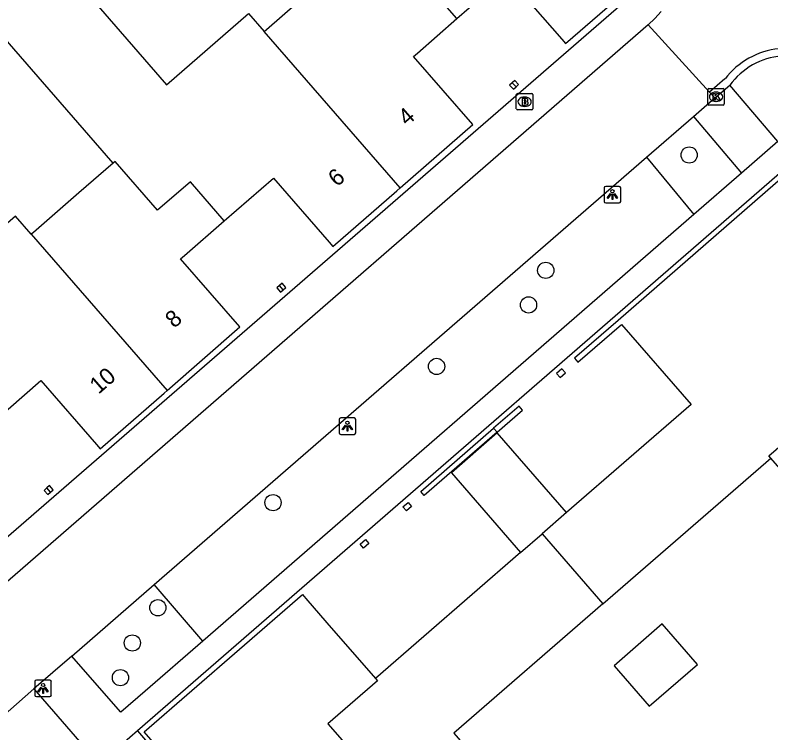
# Model space of a CAD drawing. Extents: x 155888 to 156864, y 383882 to 384671.
# Drawn here: x 156181.97 to 156227.53, y 384100.28 to 384143.54 of the extents above; entities that cross this region are included whole.
import ezdxf

# ---------------------------------------------------------------- set-up
doc = ezdxf.new("R2010")
doc.units = 0
for name, color, linetype in [('IMGEO_Boom', 7, 'Continuous'), ('IMGEO_Brandkraan', 7, 'Continuous'), ('IMGEO_Kolk', 7, 'Continuous'), ('IMGEO_Lichtpunt', 7, 'Continuous'), ('IMGEO_Pand', 7, 'Continuous'), ('IMGEO_Pand_nummerreeks', 7, 'Continuous'), ('IMGEO_Parkeervlak_open', 7, 'Continuous'), ('IMGEO_Rijbaan_lokaal_gesloten', 7, 'Continuous'), ('IMGEO_Rijbaan_lokaal_open', 7, 'Continuous'), ('IMGEO_Voetpad_open', 7, 'Continuous')]:
    doc.layers.add(name, color=color, linetype=linetype)

msp = doc.modelspace()

# ---------------------------------------------------------------- linework, layer by layer
at = {"layer": 'IMGEO_Boom'}
for centre in [(156222.605, 384135.111), (156213.959, 384128.157), (156212.921, 384126.074), (156207.375, 384122.368), (156197.517, 384114.159), (156190.572, 384107.824), (156189.033, 384105.701), (156188.318, 384103.61)]:
    msp.add_circle(centre, 0.489, dxfattribs=at)
at = {"layer": 'IMGEO_Brandkraan'}
for p, q in [((156212.259, 384138.824), (156213.111, 384138.824)), ((156212.184, 384137.898), (156212.184, 384138.75)), ((156212.672, 384138.604), (156212.697, 384138.604)), ((156213.185, 384138.75), (156213.185, 384137.898)), ((156212.695, 384138.044), (156212.67, 384138.044)), ((156213.111, 384137.824), (156212.259, 384137.824))]:
    msp.add_line(p, q, dxfattribs=at)
for points in [[(156212.259, 384138.824), (156213.111, 384138.824)], [(156212.184, 384137.898), (156212.184, 384138.75)], [(156212.532, 384138.524), (156212.532, 384138.124), (156212.745, 384138.124)], [(156212.763, 384138.524), (156212.532, 384138.524)], [(156212.711, 384138.443), (156212.657, 384138.443), (156212.657, 384138.367)], [(156212.657, 384138.367), (156212.71, 384138.367)], [(156213.185, 384138.75), (156213.185, 384137.898)], [(156212.719, 384138.291), (156212.657, 384138.291), (156212.657, 384138.21)], [(156212.657, 384138.21), (156212.719, 384138.21)], [(156213.111, 384137.824), (156212.259, 384137.824)]]:
    msp.add_lwpolyline(points, dxfattribs=at)
for centre, radius, start, end in [((156212.261, 384138.748), 0.0765, 91.552, 178.448), ((156212.261, 384138.748), 0.0765, 91.552, 178.448), ((156213.109, 384138.748), 0.0765, 1.552, 88.448), ((156213.109, 384138.748), 0.0765, 1.552, 88.448), ((156212.712, 384138.405), 0.0379, 267.8285, 90.9355), ((156212.767, 384138.379), 0.145, 59.4692, 91.5367), ((156212.792, 384138.426), 0.0922, 285.5137, 58.1501), ((156212.72, 384138.25), 0.0404, 269.8759, 90.5077), ((156212.751, 384138.375), 0.251, 268.6676, 293.5347), ((156212.797, 384138.234), 0.105, 301.3115, 78.989), ((156212.261, 384137.9), 0.0765, 181.552, 268.448), ((156212.261, 384137.9), 0.0765, 181.552, 268.448), ((156213.109, 384137.9), 0.0765, 271.552, 358.448), ((156213.109, 384137.9), 0.0765, 271.552, 358.448)]:
    msp.add_arc(centre, radius, start, end, dxfattribs=at)
for centre, major_axis, ratio, start_param, end_param in [((156212.671, 384138.324), (-0.387, 0.002), 0.722429, 4.712389, 7.853982), ((156212.696, 384138.324), (-0.39, 0.002), 0.717154, 1.570796, 4.712389)]:
    msp.add_ellipse(centre, major_axis=major_axis, ratio=ratio, start_param=start_param, end_param=end_param, dxfattribs=at)
at = {"layer": 'IMGEO_Kolk'}
for p, q in [((156223.722, 384138.194), (156223.722, 384139.046)), ((156223.797, 384139.12), (156224.649, 384139.12)), ((156224.21, 384138.9), (156224.235, 384138.9)), ((156224.723, 384139.046), (156224.723, 384138.194)), ((156224.649, 384138.12), (156223.797, 384138.12)), ((156224.233, 384138.34), (156224.208, 384138.34))]:
    msp.add_line(p, q, dxfattribs=at)
for points in [[(156223.722, 384138.194), (156223.722, 384139.046)], [(156223.797, 384139.12), (156224.649, 384139.12)], [(156224.043, 384138.82), (156224.166, 384138.82), (156224.166, 384138.669), (156224.296, 384138.82), (156224.46, 384138.82), (156224.314, 384138.669), (156224.467, 384138.42), (156224.315, 384138.42), (156224.23, 384138.584), (156224.166, 384138.517), (156224.166, 384138.42), (156224.043, 384138.42), (156224.043, 384138.82)], [(156224.723, 384139.046), (156224.723, 384138.194)], [(156224.649, 384138.12), (156223.797, 384138.12)]]:
    msp.add_lwpolyline(points, dxfattribs=at)
for centre, start, end in [((156223.799, 384139.044), 91.552, 178.448), ((156223.799, 384139.044), 91.552, 178.448), ((156224.647, 384139.044), 1.552, 88.448), ((156224.647, 384139.044), 1.552, 88.448), ((156223.799, 384138.196), 181.552, 268.448), ((156223.799, 384138.196), 181.552, 268.448), ((156224.647, 384138.196), 271.552, 358.448), ((156224.647, 384138.196), 271.552, 358.448)]:
    msp.add_arc(centre, 0.0765, start, end, dxfattribs=at)
for centre, major_axis, ratio, start_param, end_param in [((156224.209, 384138.62), (-0.387, 0.002), 0.722429, 4.712389, 7.853982), ((156224.234, 384138.62), (-0.39, 0.002), 0.717154, 1.570796, 4.712389)]:
    msp.add_ellipse(centre, major_axis=major_axis, ratio=ratio, start_param=start_param, end_param=end_param, dxfattribs=at)
at = {"layer": 'IMGEO_Lichtpunt'}
for p, q in [((156217.48, 384133.125), (156217.48, 384132.318)), ((156217.48, 384133.125), (156217.48, 384132.318)), ((156218.382, 384133.22), (156217.574, 384133.22)), ((156218.382, 384133.22), (156217.574, 384133.22)), ((156218.476, 384132.318), (156218.476, 384133.125)), ((156218.476, 384132.318), (156218.476, 384133.125)), ((156217.574, 384132.224), (156218.382, 384132.224)), ((156217.574, 384132.224), (156218.382, 384132.224)), ((156202.407, 384119.267), (156201.599, 384119.267)), ((156202.407, 384119.267), (156201.599, 384119.267)), ((156201.505, 384119.172), (156201.505, 384118.365)), ((156201.505, 384119.172), (156201.505, 384118.365)), ((156202.501, 384118.365), (156202.501, 384119.172)), ((156202.501, 384118.365), (156202.501, 384119.172)), ((156201.599, 384118.271), (156202.407, 384118.271)), ((156201.599, 384118.271), (156202.407, 384118.271)), ((156183.154, 384103.368), (156183.154, 384102.561)), ((156183.154, 384103.368), (156183.154, 384102.561)), ((156184.056, 384103.463), (156183.248, 384103.463)), ((156184.056, 384103.463), (156183.248, 384103.463)), ((156184.15, 384102.561), (156184.15, 384103.368)), ((156184.15, 384102.561), (156184.15, 384103.368)), ((156183.248, 384102.467), (156184.056, 384102.467)), ((156183.248, 384102.467), (156184.056, 384102.467))]:
    msp.add_line(p, q, dxfattribs=at)
for points in [[(156217.854, 384132.789), (156217.893, 384132.761), (156217.705, 384132.499), (156217.667, 384132.526), (156217.854, 384132.789)], [(156217.956, 384132.741), (156218.003, 384132.741), (156218.003, 384132.419), (156217.956, 384132.419), (156217.956, 384132.741)], [(156218.066, 384132.761), (156218.104, 384132.788), (156218.291, 384132.526), (156218.252, 384132.498), (156218.066, 384132.761)], [(156201.879, 384118.836), (156201.918, 384118.808), (156201.73, 384118.546), (156201.692, 384118.573), (156201.879, 384118.836)], [(156201.981, 384118.788), (156202.028, 384118.788), (156202.028, 384118.466), (156201.981, 384118.466), (156201.981, 384118.788)], [(156202.091, 384118.808), (156202.129, 384118.835), (156202.316, 384118.573), (156202.277, 384118.545), (156202.091, 384118.808)], [(156183.528, 384103.032), (156183.567, 384103.004), (156183.379, 384102.742), (156183.341, 384102.769), (156183.528, 384103.032)], [(156183.63, 384102.984), (156183.677, 384102.984), (156183.677, 384102.662), (156183.63, 384102.662), (156183.63, 384102.984)], [(156183.74, 384103.004), (156183.778, 384103.031), (156183.965, 384102.769), (156183.926, 384102.741), (156183.74, 384103.004)]]:
    msp.add_lwpolyline(points, dxfattribs=at)
for centre in [(156217.979, 384132.923), (156202.004, 384118.97), (156183.653, 384103.166)]:
    msp.add_circle(centre, 0.0994, dxfattribs=at)
for centre, start, end in [((156217.574, 384133.125), 90, 180), ((156217.574, 384133.125), 90, 180), ((156218.382, 384133.125), 0, 90), ((156218.382, 384133.125), 0, 90), ((156217.574, 384132.318), 180, 270), ((156217.574, 384132.318), 180, 270), ((156218.382, 384132.318), 270, 0), ((156218.382, 384132.318), 270, 360), ((156201.599, 384119.172), 90, 180), ((156201.599, 384119.172), 90, 180), ((156202.407, 384119.172), 0, 90), ((156202.407, 384119.172), 0, 90), ((156201.599, 384118.365), 180, 270), ((156201.599, 384118.365), 180, 270), ((156202.407, 384118.365), 270, 0), ((156202.407, 384118.365), 270, 360), ((156183.248, 384103.368), 90, 180), ((156183.248, 384103.368), 90, 180), ((156184.056, 384103.368), 0, 90), ((156184.056, 384103.368), 0, 90), ((156183.248, 384102.561), 180, 270), ((156183.248, 384102.561), 180, 270), ((156184.056, 384102.561), 270, 0), ((156184.056, 384102.561), 270, 360)]:
    msp.add_arc(centre, 0.0946, start, end, dxfattribs=at)
at = {"layer": 'IMGEO_Pand'}
for points in [[(156184.574, 384146.847), (156191.102, 384139.344), (156196.034, 384143.635), (156196.979, 384142.549)], [(156196.979, 384142.549), (156197.114, 384142.667), (156199.021, 384144.325), (156201.91, 384146.836)], [(156208.597, 384143.333), (156206.538, 384145.692), (156204.598, 384143.999), (156202.038, 384146.947), (156201.91, 384146.836)], [(156208.597, 384143.333), (156211.577, 384145.937), (156214.934, 384142.084), (156215.157, 384141.828), (156219.294, 384145.432)], [(156205.178, 384133.123), (156209.565, 384136.942), (156205.986, 384141.052), (156206.216, 384141.253), (156208.597, 384143.333)], [(156205.178, 384133.123), (156196.979, 384142.549)], [(156187.875, 384134.618), (156181.222, 384142.274)], [(156211.94, 384139.469), (156211.78, 384139.327), (156212.006, 384139.073), (156212.166, 384139.215)], [(156212.166, 384139.215), (156212.325, 384139.356), (156212.099, 384139.61), (156211.94, 384139.469)], [(156212.166, 384139.215), (156211.94, 384139.469)], [(156194.579, 384131.136), (156192.534, 384133.501), (156190.556, 384131.791), (156188.003, 384134.729), (156187.875, 384134.618)], [(156187.875, 384134.618), (156185.814, 384132.827), (156183.076, 384130.448), (156182.941, 384130.331)], [(156231.045, 384123.558), (156228.388, 384126.622), (156232.251, 384129.975), (156232.504, 384130.194), (156228.903, 384134.34), (156218.319, 384125.143), (156215.686, 384122.871), (156215.896, 384122.63), (156218.529, 384124.902), (156222.715, 384120.08), (156215.206, 384113.559)], [(156182.941, 384130.331), (156181.99, 384131.424), (156177.048, 384127.13), (156170.866, 384134.244)], [(156194.579, 384131.136), (156197.552, 384133.709), (156200.908, 384129.855), (156201.131, 384129.599), (156204.974, 384132.945), (156205.178, 384133.123)], [(156191.13, 384120.916), (156195.524, 384124.745), (156191.944, 384128.854), (156192.174, 384129.053), (156194.579, 384131.136)], [(156182.941, 384130.331), (156191.13, 384120.916)], [(156197.897, 384127.248), (156197.738, 384127.11), (156197.961, 384126.853), (156198.121, 384126.992)], [(156198.121, 384126.992), (156198.281, 384127.131), (156198.059, 384127.388), (156197.897, 384127.248)], [(156198.121, 384126.992), (156197.897, 384127.248)], [(156227.527, 384116.842), (156227.413, 384116.974), (156230.363, 384119.537), (156228.665, 384121.493), (156231.045, 384123.558)], [(156215.141, 384121.974), (156214.931, 384122.215), (156214.614, 384121.94), (156214.824, 384121.699), (156215.141, 384121.974)], [(156180.549, 384118.923), (156183.521, 384121.515), (156186.882, 384117.658), (156187.101, 384117.406), (156190.952, 384120.761), (156191.13, 384120.916)], [(156211.025, 384118.402), (156212.558, 384119.733), (156212.348, 384119.974), (156210.815, 384118.643)], [(156211.025, 384118.402), (156206.629, 384114.587), (156206.419, 384114.828), (156210.815, 384118.643)], [(156215.206, 384113.559), (156211.033, 384118.365), (156208.268, 384115.964), (156212.441, 384111.158)], [(156210.815, 384118.643), (156211.025, 384118.402)], [(156217.399, 384108.054), (156227.527, 384116.842)], [(156231.808, 384111.909), (156231.69, 384112.045), (156229.307, 384114.791), (156227.527, 384116.842)], [(156184.103, 384114.791), (156184.266, 384114.933), (156184.046, 384115.184), (156183.882, 384115.041)], [(156183.882, 384115.041), (156183.718, 384114.898), (156183.937, 384114.646), (156184.103, 384114.791)], [(156184.103, 384114.791), (156183.882, 384115.041)], [(156205.557, 384113.657), (156205.347, 384113.898), (156205.664, 384114.173), (156205.874, 384113.932), (156205.557, 384113.657)], [(156215.206, 384113.559), (156213.741, 384112.287)], [(156212.441, 384111.158), (156213.741, 384112.287)], [(156213.741, 384112.287), (156217.399, 384108.054)], [(156202.974, 384111.415), (156202.764, 384111.656), (156203.081, 384111.931), (156203.291, 384111.69), (156202.974, 384111.415)], [(156212.441, 384111.158), (156203.688, 384103.557)], [(156200.094, 384096.764), (156198.049, 384099.115), (156197.856, 384099.338), (156193.752, 384095.751), (156189.742, 384100.339), (156195.49, 384105.33), (156199.286, 384108.627), (156199.496, 384108.386), (156200.768, 384106.921), (156203.688, 384103.557)], [(156217.399, 384108.054), (156208.415, 384100.257), (156212.696, 384095.324)], [(156220.2, 384101.883), (156223.108, 384104.407), (156220.983, 384106.855), (156218.075, 384104.332), (156220.2, 384101.883)], [(156203.688, 384103.557), (156203.813, 384103.413), (156200.824, 384100.831), (156202.524, 384098.877), (156200.094, 384096.764)]]:
    msp.add_lwpolyline(points, dxfattribs=at)
at = {"layer": 'IMGEO_Parkeervlak_open'}
for points in [[(156222.856, 384137.431), (156225.769, 384134.023)], [(156220.023, 384134.972), (156222.885, 384131.519)], [(156193.282, 384105.813), (156190.357, 384109.221)]]:
    msp.add_lwpolyline(points, dxfattribs=at)
at = {"layer": 'IMGEO_Rijbaan_lokaal_gesloten'}
for points in [[(156220.134, 384142.954), (156220.538, 384143.338), (156220.911, 384143.751)], [(156220.134, 384142.954), (156131.822, 384066.268)], [(156223.837, 384138.892), (156220.134, 384142.954)], [(156224.764, 384139.697), (156223.837, 384138.892)], [(156223.837, 384138.892), (156224.147, 384138.552)], [(156222.856, 384137.431), (156224.147, 384138.552)], [(156220.023, 384134.972), (156222.856, 384137.431)], [(156190.357, 384109.221), (156220.023, 384134.972)], [(156185.393, 384104.912), (156190.357, 384109.221)], [(156185.393, 384104.912), (156183.098, 384102.929)], [(156179.022, 384099.365), (156180.638, 384100.784), (156183.098, 384102.929)]]:
    msp.add_lwpolyline(points, dxfattribs=at)
msp.add_arc((156228.516, 384136.816), 4.73, 49.5942, 142.4789, dxfattribs=at)
at = {"layer": 'IMGEO_Rijbaan_lokaal_open'}
for points in [[(156224.147, 384138.552), (156224.224, 384138.619), (156225.054, 384139.316)], [(156183.098, 384102.929), (156187.027, 384098.401)]]:
    msp.add_lwpolyline(points, dxfattribs=at)
msp.add_arc((156228.516, 384136.816), 4.27, 44.8936, 144.1672, dxfattribs=at)
at = {"layer": 'IMGEO_Voetpad_open'}
for points in [[(156219.567, 384145.116), (156177.171, 384108.334), (156176.966, 384108.553)], [(156227.956, 384135.922), (156225.054, 384139.316)], [(156227.956, 384135.922), (156225.769, 384134.023)], [(156228.952, 384134.784), (156195.288, 384105.561), (156189.338, 384100.396)], [(156225.769, 384134.023), (156222.885, 384131.519)], [(156222.885, 384131.519), (156193.282, 384105.813)], [(156193.282, 384105.813), (156189.807, 384102.795), (156188.339, 384101.53), (156186.49, 384103.635), (156185.393, 384104.912)], [(156189.338, 384100.396), (156187.027, 384098.401)], [(156189.338, 384100.396), (156193.713, 384095.326), (156201.684, 384086.153), (156205.864, 384081.345), (156221.93, 384062.847)]]:
    msp.add_lwpolyline(points, dxfattribs=at)

# ---------------------------------------------------------------- texts
at = {"layer": 'IMGEO_Pand_nummerreeks'}
for s, rotation, p in [('4', 41.0467, (156205.594, 384136.826)), ('6', 41.0467, (156201.377, 384133.155)), ('8', 41.0639, (156191.557, 384124.632)), ('10', 41.0639, (156186.999, 384120.66))]:
    msp.add_text(s, height=1, rotation=rotation, dxfattribs=at).set_placement(p)

doc.saveas('drawing.dxf')
